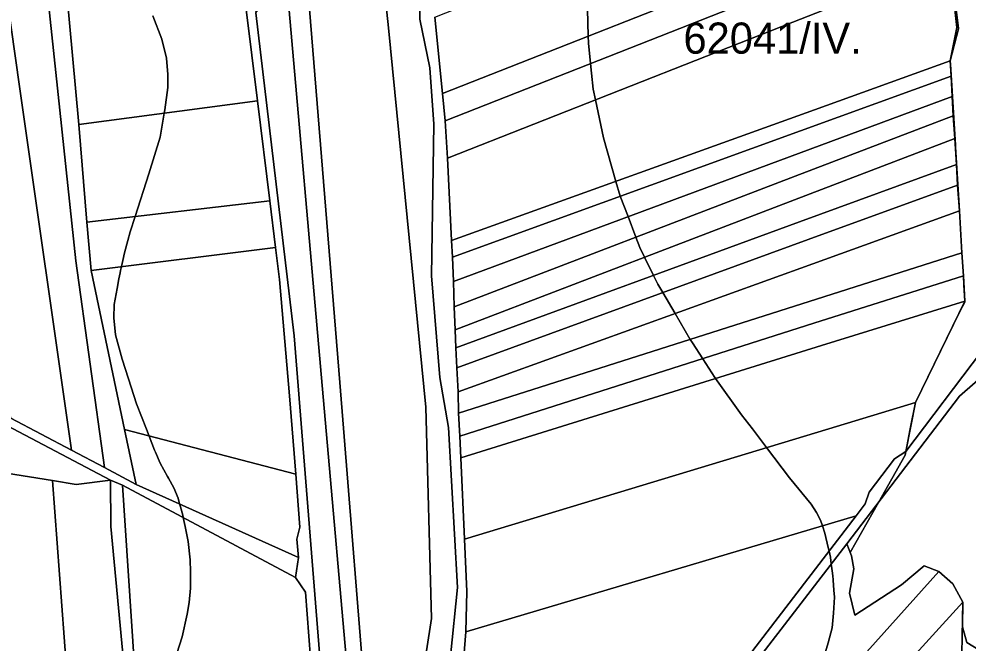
# Model space of a CAD drawing. Extents: x -521939 to -516426, y -1197857 to -1189551.
# Drawn here: x -518483.4 to -518026.2, y -1192103.1 to -1191802.5 of the extents above; entities that cross this region are included whole.
import ezdxf

# ---------------------------------------------------------------- set-up
doc = ezdxf.new("R2010")
doc.units = 0
for name, color, linetype in [('95560013', 7, 'Continuous'), ('95610013', 7, 'Continuous'), ('95630013', 7, 'Continuous'), ('95640013', 7, 'Continuous'), ('95660013', 7, 'Continuous')]:
    doc.layers.add(name, color=color, linetype=linetype)

msp = doc.modelspace()

# ---------------------------------------------------------------- linework, layer by layer
at = {"layer": '95560013'}
for points in [[(-518556.44, -1191349.16), (-518528.88, -1191526.36), (-518508.28, -1191658.81), (-518483.09, -1191835.12), (-518458.07, -1192010.24), (-518487.38, -1191994.82), (-518498.99, -1191895.13), (-518520.13, -1191713.61), (-518541.27, -1191532.09), (-518562.41, -1191350.57)], [(-518550.53, -1191347.83), (-518534.55, -1191404.6), (-518511.67, -1191505.47), (-518504.02, -1191551.95), (-518475.27, -1191737.43), (-518456.08, -1191919), (-518442.18, -1192018.62), (-518458.07, -1192010.24), (-518483.09, -1191835.12), (-518508.28, -1191658.81), (-518528.88, -1191526.36), (-518556.44, -1191349.16)]]:
    msp.add_lwpolyline(points, close=True, dxfattribs=at)
at = {"layer": '95610013'}
for points in [[(-518038.61, -1191705.3), (-518039.39, -1191733.78), (-518038.39, -1191743.43), (-518111.96, -1191772.41), (-518279.46, -1191838.39), (-518283.1, -1191801.62), (-518115.47, -1191735.58)], [(-518464.87, -1191741.35), (-518382.15, -1191731.8), (-518368.51, -1191841.95), (-518454.59, -1191853.4)], [(-518038.39, -1191743.43), (-518037.01, -1191756.49), (-518110.85, -1191785.59), (-518278.17, -1191851.53), (-518279.46, -1191838.39), (-518111.96, -1191772.41)], [(-518278.17, -1191851.53), (-518110.85, -1191785.59), (-518037.01, -1191756.49), (-518035.12, -1191774.44), (-518110.62, -1191804.12), (-518277.01, -1191869.53)], [(-518277.01, -1191869.53), (-518110.62, -1191804.12), (-518035.12, -1191774.44), (-518031.59, -1191806.67), (-518034.81, -1191822.72), (-518100.19, -1191846.28), (-518274.99, -1191909.27)], [(-518307.55, -1191787.05), (-518305.35, -1191806.74), (-518287.42, -1191989.44), (-518284.75, -1192091.34), (-518292.25, -1192140.07), (-518291.06, -1192151.72), (-518277.44, -1192285.07), (-518284.92, -1192287.57), (-518303.55, -1192291.15), (-518314.83, -1192151.68), (-518328.91, -1191977.59), (-518343.95, -1191791.63)], [(-518303.55, -1192291.15), (-518309.77, -1192291.81), (-518322.59, -1192146.47), (-518338.17, -1191969.84), (-518353.78, -1191792.87), (-518343.95, -1191791.63), (-518328.91, -1191977.59), (-518314.83, -1192151.68)], [(-518309.77, -1192291.81), (-518320.04, -1192293.11), (-518324, -1192289.89), (-518336.18, -1192137.91), (-518350.83, -1191955.11), (-518369.24, -1191799.59), (-518365.14, -1191794.33), (-518353.78, -1191792.87), (-518338.17, -1191969.84), (-518322.59, -1192146.47)], [(-518274.99, -1191909.27), (-518100.19, -1191846.28), (-518034.81, -1191822.72), (-518034.38, -1191830.07), (-518106.99, -1191856.4), (-518274.63, -1191917.19)], [(-518034.38, -1191830.07), (-518033.85, -1191839.8), (-518102.33, -1191865.2), (-518274.15, -1191928.93), (-518274.63, -1191917.19), (-518106.99, -1191856.4)], [(-518454.59, -1191853.4), (-518368.51, -1191841.95), (-518362.56, -1191890.14), (-518450.7, -1191900.44)], [(-518274.15, -1191928.93), (-518102.33, -1191865.2), (-518033.85, -1191839.8), (-518033.34, -1191849.1), (-518109.53, -1191878.26), (-518273.72, -1191941.1)], [(-518273.72, -1191941.1), (-518109.53, -1191878.26), (-518033.34, -1191849.1), (-518032.64, -1191860.06), (-518102.29, -1191886.72), (-518273.28, -1191952.17)], [(-518273.28, -1191952.17), (-518102.29, -1191886.72), (-518032.64, -1191860.06), (-518031.81, -1191872.61), (-518107.33, -1191900.28), (-518272.89, -1191960.94)], [(-518107.33, -1191900.28), (-518031.81, -1191872.61), (-518031.25, -1191882.52), (-518103.21, -1191908.77), (-518272.46, -1191970.51), (-518272.89, -1191960.94)], [(-518272.46, -1191970.51), (-518103.21, -1191908.77), (-518031.25, -1191882.52), (-518030.38, -1191894.92), (-518100.99, -1191920.43), (-518271.91, -1191982.18)], [(-518450.7, -1191900.44), (-518362.56, -1191890.14), (-518359.88, -1191912.56), (-518448.71, -1191923.59)], [(-518271.91, -1191982.18), (-518100.99, -1191920.43), (-518030.38, -1191894.92), (-518029.14, -1191915.1), (-518102.67, -1191938.54), (-518271.72, -1191992.43)], [(-518359.88, -1191912.56), (-518357.94, -1191927.95), (-518353.13, -1191983.99), (-518350.01, -1192021.8), (-518432.53, -1192000.31), (-518448.71, -1191923.59)], [(-518029.14, -1191915.1), (-518028.46, -1191926.18), (-518100.44, -1191949.1), (-518271, -1192003.41), (-518271.72, -1191992.43), (-518102.67, -1191938.54)], [(-518028.46, -1191926.18), (-518027.73, -1191938.4), (-518096.81, -1191959.86), (-518270.54, -1192013.83), (-518271, -1192003.41), (-518100.44, -1191949.1)], [(-518027.73, -1191938.4), (-518051.56, -1191987.26), (-518093.21, -1191999.88), (-518268.82, -1192053.09), (-518270.54, -1192013.83), (-518096.81, -1191959.86)], [(-518267.68, -1192078.26), (-518268.82, -1192053.09), (-518093.21, -1191999.88), (-518051.56, -1191987.26), (-518056.12, -1192010.8), (-518061.62, -1192014.36), (-518073.91, -1192030.36), (-518075.76, -1192036.07), (-518080.12, -1192041.74), (-518268.08, -1192097.64)], [(-518348.78, -1192061.86), (-518426.98, -1192026.71), (-518432.53, -1192000.31), (-518350.01, -1192021.8), (-518348.09, -1192047.23), (-518349.5, -1192053.03)], [(-518467.2, -1192024.87), (-518453.83, -1192205.92), (-518446.24, -1192308.7), (-518473.81, -1192312.07), (-518482.19, -1192198.12), (-518495.32, -1192019.58), (-518489.35, -1192021.32)], [(-518467.2, -1192024.87), (-518455.87, -1192026.74), (-518439.37, -1192024.6), (-518439.2, -1192046.97), (-518433.03, -1192111.71), (-518430.38, -1192158.5), (-518418.17, -1192305.22), (-518446.24, -1192308.7), (-518453.83, -1192205.92)], [(-518080.12, -1192041.74), (-518155.32, -1192139.69), (-518272.87, -1192172.21), (-518272.25, -1192149.92), (-518268.08, -1192097.64)], [(-518261.64, -1192315.58), (-518262.96, -1192305.09), (-518264.35, -1192294.45), (-518264.63, -1192290.93), (-518264.08, -1192288.87), (-518252.08, -1192273.08), (-518130.19, -1192114.62), (-518084.56, -1192055.3), (-518082.39, -1192061.11), (-518081.28, -1192067.38), (-518083.39, -1192079.13), (-518080.71, -1192089.58), (-518058.25, -1192075.03), (-518047.38, -1192065.85), (-518040.27, -1192068.64), (-518140.09, -1192179.99)], [(-518258.96, -1192336.56), (-518261.64, -1192315.58), (-518140.09, -1192179.99), (-518040.27, -1192068.64), (-518033.52, -1192074.51), (-518028.72, -1192083.39), (-518138.97, -1192204.62)], [(-518028.72, -1192083.39), (-518029.53, -1192124.74), (-518132.91, -1192235.21), (-518255.1, -1192365.78), (-518258.96, -1192336.56), (-518138.97, -1192204.62)]]:
    msp.add_lwpolyline(points, close=True, dxfattribs=at)
at = {"layer": '95630013'}
msp.add_lwpolyline([(-518019.65, -1191962.72), (-518056.12, -1192010.8), (-518051.56, -1191987.26), (-518027.73, -1191938.4), (-518028.46, -1191926.18), (-518029.14, -1191915.1), (-518030.38, -1191894.92), (-518031.25, -1191882.52), (-518031.81, -1191872.61), (-518032.64, -1191860.06), (-518033.34, -1191849.1), (-518033.85, -1191839.8), (-518034.38, -1191830.07), (-518034.81, -1191822.72), (-518031.59, -1191806.67), (-518035.12, -1191774.44)], dxfattribs=at)
at = {"layer": '95640013'}
for points in [[(-518507.78, -1191452.68), (-518505.21, -1191461.73), (-518492.98, -1191533.04), (-518481.26, -1191583.91), (-518477.36, -1191595.24), (-518479.16, -1191647.79), (-518473.02, -1191676.18), (-518469.66, -1191697.37), (-518466.4, -1191722.26), (-518464.87, -1191741.35), (-518454.59, -1191853.4), (-518450.7, -1191900.44), (-518448.71, -1191923.59), (-518432.53, -1192000.31), (-518426.98, -1192026.71), (-518442.18, -1192018.62), (-518456.08, -1191919), (-518475.27, -1191737.43), (-518504.02, -1191551.95), (-518511.67, -1191505.47), (-518534.55, -1191404.6), (-518550.53, -1191347.83), (-518539.79, -1191345.38), (-518523.95, -1191394.84)], [(-518285.42, -1191826.12), (-518283.49, -1191853.16), (-518284.63, -1191926.19), (-518280.69, -1191975.27), (-518276.42, -1191999.25), (-518272.1, -1192076.35), (-518275.47, -1192109.47), (-518276.97, -1192150.12), (-518291.06, -1192151.72), (-518292.25, -1192140.07), (-518284.75, -1192091.34), (-518287.42, -1191989.44), (-518305.35, -1191806.74), (-518307.55, -1191787.05), (-518293.44, -1191785.24), (-518290.41, -1191787.66), (-518290.26, -1191802.68)], [(-518417.67, -1192167.63), (-518413.57, -1192211.06), (-518410.84, -1192238.5), (-518402.53, -1192303.29), (-518418.17, -1192305.22), (-518430.38, -1192158.5), (-518433.03, -1192111.71), (-518439.2, -1192046.97), (-518439.37, -1192024.6), (-518433.62, -1192027.04), (-518427.94, -1192112.02), (-518422.39, -1192159.94), (-518420.04, -1192163.76)], [(-518433.62, -1192027.04), (-518350.12, -1192071.56), (-518345.44, -1192078.61), (-518343.05, -1192110.36), (-518348.03, -1192112.23), (-518427.94, -1192112.02)]]:
    msp.add_lwpolyline(points, close=True, dxfattribs=at)
for points in [[(-518458.86, -1191359.62), (-518439.99, -1191421.45), (-518435.22, -1191438.67), (-518396.87, -1191613.34), (-518387.26, -1191657.11), (-518380.58, -1191707.99), (-518370.89, -1191786.28), (-518369.24, -1191799.59), (-518350.83, -1191955.11), (-518336.18, -1192137.91)], [(-518343.05, -1192110.36), (-518345.44, -1192078.61), (-518350.12, -1192071.56), (-518348.78, -1192061.86), (-518349.5, -1192053.03), (-518348.09, -1192047.23), (-518350.01, -1192021.8), (-518353.13, -1191983.99), (-518357.94, -1191927.95), (-518359.88, -1191912.56), (-518362.56, -1191890.14), (-518368.51, -1191841.95), (-518382.15, -1191731.8), (-518388.12, -1191683.62), (-518389.54, -1191673.05), (-518392.61, -1191655.06), (-518394.56, -1191652.47), (-518397.54, -1191635.81), (-518410.47, -1191583.23), (-518418.21, -1191537.31), (-518421.64, -1191520.99), (-518439.4, -1191439.86), (-518443.9, -1191423.5), (-518457.15, -1191381.15)], [(-518275.47, -1192109.47), (-518272.1, -1192076.35), (-518276.42, -1191999.25), (-518280.69, -1191975.27), (-518284.63, -1191926.19), (-518283.49, -1191853.16), (-518285.42, -1191826.12), (-518290.26, -1191802.68), (-518290.41, -1191787.66)], [(-518283.1, -1191801.62), (-518279.46, -1191838.39), (-518278.17, -1191851.53), (-518277.01, -1191869.53), (-518274.99, -1191909.27), (-518274.63, -1191917.19), (-518274.15, -1191928.93), (-518273.72, -1191941.1), (-518273.28, -1191952.17), (-518272.89, -1191960.94), (-518272.46, -1191970.51), (-518271.91, -1191982.18), (-518271.72, -1191992.43), (-518271, -1192003.41), (-518270.54, -1192013.83), (-518268.82, -1192053.09), (-518267.68, -1192078.26), (-518268.08, -1192097.64), (-518272.25, -1192149.92)], [(-517991.23, -1191950.13), (-518030.31, -1191984.26), (-518084.56, -1192055.3), (-518130.19, -1192114.62)], [(-518029.53, -1192124.74), (-518028.72, -1192083.39), (-518033.52, -1192074.51), (-518040.27, -1192068.64), (-518047.38, -1192065.85), (-518058.25, -1192075.03), (-518080.71, -1192089.58), (-518083.39, -1192079.13), (-518081.28, -1192067.38), (-518082.39, -1192061.11), (-518084.56, -1192055.3), (-518030.31, -1191984.26), (-517991.23, -1191950.13), (-517988.45, -1191949.05), (-517977.06, -1191987.74), (-517949.43, -1192095.84), (-517943.23, -1192113.96)], [(-518155.32, -1192139.69), (-518080.12, -1192041.74), (-518075.76, -1192036.07), (-518073.91, -1192030.36), (-518061.62, -1192014.36), (-518056.12, -1192010.8), (-518019.65, -1191962.72)], [(-518487.38, -1191994.82), (-518458.07, -1192010.24), (-518442.18, -1192018.62), (-518426.98, -1192026.71), (-518348.78, -1192061.86), (-518350.12, -1192071.56), (-518433.62, -1192027.04), (-518439.37, -1192024.6), (-518539.66, -1191971.83)], [(-518539.66, -1191971.83), (-518439.37, -1192024.6), (-518455.87, -1192026.74), (-518467.2, -1192024.87), (-518489.35, -1192021.32)]]:
    msp.add_lwpolyline(points, dxfattribs=at)
at = {"layer": '95660013'}
for points in [[(-518035.79, -1191767.85), (-518030.77, -1191806.88), (-518030.85, -1191807.2), (-518034.81, -1191822.72), (-518034.71, -1191824.28), (-518032.32, -1191863.24), (-518032.26, -1191864.31), (-518030.38, -1191894.92), (-518029.14, -1191915.1), (-518028.46, -1191926.18), (-518028.2, -1191930.57), (-518027.72, -1191938.4), (-518027.69, -1191938.85), (-518030.17, -1191943.4), (-518051.56, -1191987.26), (-518054.03, -1192000), (-518055.67, -1192008.5), (-518056.11, -1192010.8), (-518056.47, -1192012.64), (-518069.41, -1192035.46), (-518083.01, -1192059.45), (-518082.39, -1192061.11), (-518081.28, -1192067.38), (-518083.39, -1192079.13), (-518080.71, -1192089.58), (-518058.25, -1192075.03), (-518047.38, -1192065.85), (-518040.27, -1192068.64), (-518033.52, -1192074.51), (-518028.72, -1192083.39), (-518028.95, -1192095.34), (-518026.76, -1192102.77), (-518021.07, -1192106.3)], [(-518021.07, -1192106.3), (-518026.76, -1192102.77), (-518028.95, -1192095.34), (-518028.72, -1192083.39), (-518033.52, -1192074.51), (-518040.27, -1192068.64), (-518047.38, -1192065.85), (-518058.25, -1192075.03), (-518080.71, -1192089.58), (-518083.39, -1192079.13), (-518081.28, -1192067.38), (-518082.39, -1192061.11), (-518083.01, -1192059.45), (-518069.41, -1192035.46), (-518056.47, -1192012.64), (-518056.11, -1192010.8), (-518055.67, -1192008.5), (-518054.03, -1192000), (-518051.56, -1191987.26), (-518030.17, -1191943.4), (-518027.69, -1191938.85), (-518027.72, -1191938.4), (-518028.2, -1191930.57), (-518028.46, -1191926.18), (-518029.14, -1191915.1), (-518030.38, -1191894.92), (-518032.26, -1191864.31), (-518032.32, -1191863.24), (-518034.71, -1191824.28), (-518034.81, -1191822.72), (-518030.85, -1191807.2), (-518030.77, -1191806.88), (-518035.79, -1191767.85)], [(-518418.87, -1191801.05), (-518414.53, -1191812.32), (-518412.42, -1191821.47), (-518411.71, -1191829.22), (-518411.71, -1191835.56), (-518413.12, -1191846.35), (-518413.4, -1191847.92), (-518415.47, -1191859.5), (-518420.87, -1191877.11), (-518427.45, -1191897.72), (-518429.79, -1191905.04), (-518430.94, -1191909.18), (-518432.6, -1191915.14), (-518433.41, -1191918.81), (-518434.06, -1191921.77), (-518434.18, -1191922.33), (-518434.48, -1191923.7), (-518434.72, -1191924.76), (-518435.27, -1191927.71), (-518436.12, -1191932.27), (-518437.53, -1191940.02), (-518437.77, -1191946.47), (-518436.95, -1191954.57), (-518433.66, -1191966.31), (-518430.59, -1191975.87), (-518426.73, -1191987.91), (-518422.02, -1192000.02), (-518420.71, -1192003.39), (-518418.05, -1192010.25), (-518417.7, -1192011.15), (-518415.47, -1192016.43), (-518411.83, -1192022.88), (-518411.37, -1192023.71), (-518408.78, -1192028.4), (-518406.78, -1192033.33), (-518406.04, -1192036.12), (-518405.67, -1192037.5), (-518404.55, -1192041.43), (-518404.28, -1192042.68), (-518403.38, -1192046.89), (-518401.85, -1192054.11), (-518400.91, -1192063.03), (-518400.86, -1192068.85), (-518400.8, -1192076.64), (-518401.44, -1192083.51), (-518402.38, -1192089.14), (-518404.73, -1192100.17), (-518408.59, -1192112.07)], [(-518408.59, -1192112.07), (-518404.73, -1192100.17), (-518402.38, -1192089.14), (-518401.44, -1192083.51), (-518400.8, -1192076.64), (-518400.86, -1192068.85), (-518400.91, -1192063.03), (-518401.85, -1192054.11), (-518403.38, -1192046.89), (-518404.28, -1192042.68), (-518404.55, -1192041.43), (-518405.67, -1192037.5), (-518406.04, -1192036.12), (-518406.78, -1192033.33), (-518408.78, -1192028.4), (-518411.37, -1192023.71), (-518411.83, -1192022.88), (-518415.47, -1192016.43), (-518417.7, -1192011.15), (-518418.05, -1192010.25), (-518420.71, -1192003.39), (-518422.02, -1192000.02), (-518426.73, -1191987.91), (-518430.59, -1191975.87), (-518433.66, -1191966.31), (-518436.95, -1191954.57), (-518437.77, -1191946.47), (-518437.53, -1191940.02), (-518436.12, -1191932.27), (-518435.27, -1191927.71), (-518434.72, -1191924.76), (-518434.48, -1191923.7), (-518434.18, -1191922.33), (-518434.06, -1191921.77), (-518433.41, -1191918.81), (-518432.6, -1191915.14), (-518430.94, -1191909.18), (-518429.79, -1191905.04), (-518427.45, -1191897.72), (-518420.87, -1191877.11), (-518415.47, -1191859.5), (-518413.4, -1191847.92), (-518413.12, -1191846.35), (-518411.71, -1191835.56), (-518411.71, -1191829.22), (-518412.42, -1191821.47), (-518414.53, -1191812.32), (-518418.87, -1191801.05)], [(-518094.85, -1192107.39), (-518093.67, -1192103.02), (-518091.72, -1192095.8), (-518090.97, -1192088.72), (-518090.53, -1192081.03), (-518090.79, -1192077.65), (-518091.15, -1192072.85), (-518091.2, -1192072.41), (-518091.39, -1192070.88), (-518091.57, -1192069.43), (-518092, -1192065.99), (-518092.11, -1192065.12), (-518092.54, -1192061.72), (-518093.19, -1192058.77), (-518093.58, -1192057.03), (-518095.2, -1192050.13), (-518096.39, -1192046.58), (-518097.29, -1192043.87), (-518099.14, -1192040.28), (-518101.75, -1192036.22), (-518112.18, -1192023.47), (-518123.25, -1192008.98), (-518123.34, -1192008.86), (-518130.1, -1192000), (-518135.37, -1191993.1), (-518147.8, -1191975.7), (-518148.12, -1191975.25), (-518154.05, -1191966.17), (-518159.01, -1191958.56), (-518160.03, -1191956.83), (-518167.36, -1191944.41), (-518173.3, -1191934.34), (-518175.7, -1191930.28), (-518177.75, -1191926.08), (-518182.05, -1191917.25), (-518184.28, -1191912.66), (-518186.21, -1191907.61), (-518190, -1191897.72), (-518193.78, -1191887.85), (-518195.84, -1191880.75), (-518201.9, -1191859.8), (-518205.71, -1191841.5), (-518206.77, -1191836.39), (-518207.58, -1191828.55), (-518208.06, -1191823.9), (-518209.08, -1191814.13), (-518209.16, -1191810.7), (-518209.48, -1191797.9)], [(-518209.48, -1191797.9), (-518209.16, -1191810.7), (-518209.08, -1191814.13), (-518208.06, -1191823.9), (-518207.58, -1191828.55), (-518206.77, -1191836.39), (-518205.71, -1191841.5), (-518201.9, -1191859.8), (-518195.84, -1191880.75), (-518193.78, -1191887.85), (-518190, -1191897.72), (-518186.21, -1191907.61), (-518184.28, -1191912.66), (-518182.05, -1191917.25), (-518177.75, -1191926.08), (-518175.7, -1191930.28), (-518173.3, -1191934.34), (-518167.36, -1191944.41), (-518160.03, -1191956.83), (-518159.01, -1191958.56), (-518154.05, -1191966.17), (-518148.12, -1191975.25), (-518147.8, -1191975.7), (-518135.37, -1191993.1), (-518130.1, -1192000), (-518123.34, -1192008.86), (-518123.25, -1192008.98), (-518112.18, -1192023.47), (-518101.75, -1192036.22), (-518099.14, -1192040.28), (-518097.29, -1192043.87), (-518096.39, -1192046.58), (-518095.2, -1192050.13), (-518093.58, -1192057.03), (-518093.19, -1192058.77), (-518092.54, -1192061.72), (-518092.11, -1192065.12), (-518092, -1192065.99), (-518091.57, -1192069.43), (-518091.39, -1192070.88), (-518091.2, -1192072.41), (-518091.15, -1192072.85), (-518090.79, -1192077.65), (-518090.53, -1192081.03), (-518090.97, -1192088.72), (-518091.72, -1192095.8), (-518093.67, -1192103.02), (-518094.85, -1192107.39)]]:
    msp.add_lwpolyline(points, dxfattribs=at)

# ---------------------------------------------------------------- texts
msp.add_text('62041/IV.', height=15, rotation=0, dxfattribs=at).set_placement((-518163.31, -1191819.25))

doc.saveas('drawing.dxf')
